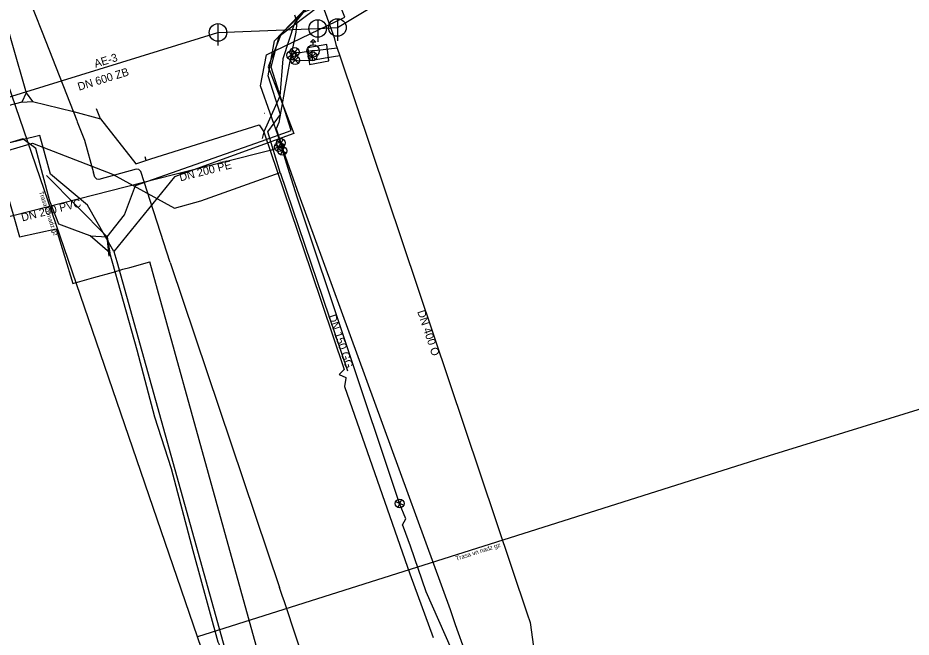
# Model space of a CAD drawing. Extents: x -493753 to -49291, y -1127285 to -112662.
# Drawn here: x -493544.7 to -493443.1, y -1126852.4 to -1126782.1 of the extents above; entities that cross this region are included whole.
import ezdxf

# ---------------------------------------------------------------- set-up
doc = ezdxf.new("R2010")
doc.units = 0
for name, color, linetype in [('Vrstva 1', 7, 'Continuous'), ('Vrstva 11', 7, 'Continuous'), ('Vrstva 12', 7, 'Continuous'), ('Vrstva 15', 7, 'Continuous'), ('Vrstva 17', 7, 'Continuous'), ('Vrstva 19', 7, 'Continuous'), ('Vrstva 20', 7, 'Continuous'), ('Vrstva 22', 7, 'Continuous'), ('Vrstva 24', 7, 'Continuous'), ('Vrstva 25', 7, 'Continuous'), ('Vrstva 26', 7, 'Continuous'), ('Vrstva 35', 7, 'Continuous'), ('Vrstva 39', 7, 'Continuous'), ('Vrstva 6', 7, 'Continuous'), ('Vrstva 9', 7, 'Continuous')]:
    doc.layers.add(name, color=color, linetype=linetype)

# ---------------------------------------------------------------- blocks, each defined once
blk = doc.blocks.new('_UZAVE')
at = {"layer": 'Vrstva 1'}
for p, q in [((-0.035, -0.035), (0.035, 0.035)), ((0.035, -0.035), (-0.035, 0.035))]:
    blk.add_line(p, q, dxfattribs=at)
for radius in [0.05, 0.0025]:
    blk.add_circle((0, 0), radius, dxfattribs=at)
blk = doc.blocks.new('_SACHT')
at = {"layer": 'Vrstva 1'}
blk.add_line((0, 0.035), (0, 0.05), dxfattribs=at)
blk.add_lwpolyline([(-0.015, 0.05), (0, 0.065), (0.015, 0.05), (0.0025, 0.05)], close=True, dxfattribs=at)
blk.add_circle((0, 0), 0.035, dxfattribs=at)
blk = doc.blocks.new('_SACH0')
at = {"layer": 'Vrstva 1'}
blk.add_line((0, 0.05), (0, -0.075), dxfattribs=at)
blk.add_circle((0, 0), 0.05, dxfattribs=at)

msp = doc.modelspace()

# ---------------------------------------------------------------- linework, layer by layer
at = {"layer": 'Vrstva 1'}
for p, q in [((-493527.35, -1126809.84), (-493527.27, -1126810.09)), ((-493527.27, -1126810.09), (-493514.91, -1126846.81))]:
    msp.add_line(p, q, dxfattribs=at)
for points in [[(-493393.38, -1126991.88), (-493403.57, -1126997.06), (-493408.72, -1126999.68), (-493421.9, -1127006.38), (-493451.16, -1126957.48), (-493453.5, -1126951.96), (-493486.26, -1126874.64), (-493487, -1126872.89), (-493487.52, -1126871.61), (-493487.88, -1126870.61), (-493487.89, -1126870.58), (-493488.33, -1126869.34), (-493488.49, -1126868.9), (-493493.92, -1126853.77), (-493494.71, -1126851.57), (-493494.94, -1126850.93), (-493495.49, -1126849.33), (-493512.69, -1126802.2), (-493517.09, -1126789.79), (-493516.41, -1126786.25), (-493507.48, -1126781.99), (-493508.14, -1126780.34), (-493515.01, -1126760.11)], [(-493545.25, -1126775.16), (-493545.2, -1126775.3), (-493544.69, -1126776.61), (-493544.34, -1126777.48), (-493543.65, -1126779.26), (-493541.92, -1126783.67), (-493537.99, -1126793.72), (-493537.93, -1126793.87)], [(-493552.89, -1126777.99), (-493552.72, -1126778.58), (-493545.07, -1126804.92), (-493544.49, -1126806.95), (-493540.33, -1126806.05), (-493538.43, -1126812.26), (-493536.06, -1126811.58), (-493533.82, -1126810.94), (-493532.86, -1126810.67), (-493532.73, -1126810.63), (-493531.96, -1126810.42), (-493529.68, -1126809.77)], [(-493537.93, -1126793.87), (-493537.11, -1126795.97), (-493536.08, -1126799.67)], [(-493527.35, -1126809.84), (-493530.69, -1126799.5), (-493530.94, -1126799.27), (-493531.23, -1126799.24), (-493535.46, -1126800.43), (-493535.71, -1126800.37), (-493535.92, -1126800.15), (-493536.08, -1126799.67)], [(-493321.71, -1127171.3), (-493355.7, -1127126.12), (-493396.16, -1127072.91), (-493440.36, -1127015.46), (-493443.8, -1127011.63), (-493444.46, -1127010.85), (-493446.49, -1127008.27), (-493452.76, -1127000), (-493477.07, -1126967.92), (-493488.61, -1126953.19), (-493508.76, -1126886.04), (-493510.25, -1126878.84), (-493511.22, -1126875.6), (-493511.24, -1126875.56), (-493513.66, -1126867.49), (-493514.58, -1126864.18), (-493529.68, -1126809.77)], [(-493510.11, -1126861.24), (-493510.21, -1126860.93), (-493514.37, -1126848.44), (-493514.62, -1126847.69), (-493514.91, -1126846.81)]]:
    msp.add_lwpolyline(points, dxfattribs=at)
at = {"layer": 'Vrstva 11'}
for points in [[(-493391.29, -1126748.6), (-493406.26, -1126753.68), (-493434.32, -1126750.53), (-493463.4, -1126761.72), (-493469.71, -1126766.76), (-493508.82, -1126780.08), (-493512.23, -1126781.43), (-493514.74, -1126783.85), (-493516.23, -1126787.62), (-493513.31, -1126795.21), (-493526.86, -1126800.13), (-493533.75, -1126808.59)], [(-493533.75, -1126808.59), (-493536.77, -1126803.34), (-493540.96, -1126799.8), (-493542.18, -1126795.43), (-493570.84, -1126802.44), (-493575.99, -1126803.69)], [(-493513.31, -1126795.21), (-493526.86, -1126800.13), (-493533.75, -1126808.59)], [(-493513.31, -1126795.21), (-493526.86, -1126800.13), (-493533.75, -1126808.59)], [(-493533.75, -1126808.59), (-493533.42, -1126809.75)], [(-493533.42, -1126809.75), (-493513.01, -1126882.98), (-493502.23, -1126919.46), (-493495.95, -1126941.27), (-493489.31, -1126964.34), (-493485.28, -1126966.64)]]:
    msp.add_lwpolyline(points, dxfattribs=at)
at = {"layer": 'Vrstva 12'}
for points in [[(-493538.22, -1126806.17), (-493540.02, -1126805.49), (-493541.05, -1126802.89), (-493542.65, -1126796.89), (-493544.12, -1126795.81), (-493550.06, -1126797.58), (-493555.41, -1126799.32), (-493561.25, -1126800.62)], [(-493536.47, -1126806.83), (-493538.22, -1126806.17)], [(-493534.22, -1126808.77), (-493536.47, -1126806.83)], [(-493521.71, -1126853.4), (-493521.89, -1126853.02), (-493524.73, -1126842.64), (-493527.19, -1126833.32), (-493529.1, -1126827.43), (-493531.11, -1126819.83), (-493534.22, -1126808.77)]]:
    msp.add_lwpolyline(points, dxfattribs=at)
at = {"layer": 'Vrstva 15'}
for p, q in [((-493508.34, -1126783.15), (-493499.28, -1126777.71)), ((-493546.35, -1126791.26), (-493521.92, -1126783.71)), ((-493521.92, -1126783.71), (-493510.58, -1126783.26)), ((-493510.58, -1126783.26), (-493508.34, -1126783.15))]:
    msp.add_line(p, q, dxfattribs=at)
at = {"layer": 'Vrstva 20'}
for p, q in [((-493508.37, -1126785.51), (-493509.97, -1126785.67)), ((-493508.37, -1126785.51), (-493508.08, -1126786.38)), ((-493513.6, -1126786.31), (-493513.72, -1126786.74)), ((-493513.72, -1126786.74), (-493513.15, -1126786.87)), ((-493513.53, -1126785.87), (-493513.6, -1126786.31)), ((-493513.53, -1126785.87), (-493513.2, -1126785.93)), ((-493513.2, -1126785.93), (-493512.56, -1126786.01)), ((-493511.25, -1126785.81), (-493512.56, -1126786.01)), ((-493511.17, -1126786.89), (-493511.18, -1126786.42)), ((-493509.75, -1126786.65), (-493511.17, -1126786.89)), ((-493508.08, -1126786.38), (-493509.75, -1126786.65)), ((-493513.15, -1126786.87), (-493512.56, -1126786.93)), ((-493511.17, -1126786.89), (-493512.56, -1126786.93)), ((-493515.01, -1126796.73), (-493515.84, -1126797.08)), ((-493514.74, -1126796.71), (-493515.01, -1126796.73)), ((-493514.77, -1126796.27), (-493514.74, -1126796.71)), ((-493514.74, -1126796.71), (-493514.6, -1126797.17)), ((-493515.84, -1126797.08), (-493526.82, -1126799.86)), ((-493514.6, -1126797.17), (-493513.83, -1126799.61)), ((-493501.26, -1126837.25), (-493501.35, -1126837.02))]:
    msp.add_line(p, q, dxfattribs=at)
for points in [[(-493517.57, -1126763.03), (-493516.2, -1126763.47), (-493508.72, -1126784.27), (-493508.52, -1126785.08), (-493508.37, -1126785.51)], [(-493513.21, -1126781.69), (-493512.97, -1126782.55), (-493513.08, -1126783.68), (-493513.53, -1126785.87)], [(-493509.97, -1126785.67), (-493510.92, -1126785.8), (-493511.1, -1126785.81), (-493511.25, -1126785.81)], [(-493513.72, -1126786.74), (-493513.95, -1126787.97), (-493514.99, -1126793.95), (-493515.32, -1126794.65), (-493514.77, -1126796.27)], [(-493511.18, -1126786.42), (-493511.2, -1126786.15), (-493511.25, -1126785.81)], [(-493508.08, -1126786.38), (-493486.74, -1126849.8), (-493486.41, -1126850.77)], [(-493526.82, -1126799.86), (-493548.86, -1126805.45), (-493554.26, -1126806.96), (-493563.36, -1126808.9), (-493563.61, -1126808.94)], [(-493513.83, -1126799.61), (-493512.93, -1126802.51), (-493501.49, -1126836.64), (-493501.35, -1126837.02)], [(-493481.22, -1126879.4), (-493481.4, -1126879.14), (-493482.12, -1126878.04), (-493488.66, -1126868.52), (-493494.64, -1126855.42), (-493498.24, -1126847.28), (-493500.01, -1126842.1), (-493500.81, -1126839.94), (-493500.94, -1126839.66), (-493500.57, -1126838.98), (-493501.26, -1126837.25)], [(-493486.41, -1126850.77), (-493484.91, -1126861.87), (-493484.36, -1126863.59)]]:
    msp.add_lwpolyline(points, dxfattribs=at)
msp.add_lwpolyline([(-493511.71, -1126785.46), (-493511.51, -1126787.34), (-493509.32, -1126786.92), (-493509.56, -1126785.07)], close=True, dxfattribs=at)
at = {"layer": 'Vrstva 25'}
for p, q in [((-493544.23, -1126791.62), (-493543, -1126791.57)), ((-493535.27, -1126793.54), (-493535.74, -1126792.39)), ((-493516.69, -1126795), (-493516.9, -1126795.77)), ((-493530.08, -1126798.25), (-493530.22, -1126797.85)), ((-493507.56, -1126822.02), (-493508.15, -1126822.58))]:
    msp.add_line(p, q, dxfattribs=at)
for points in [[(-493545.91, -1126734.71), (-493545.66, -1126735.36), (-493539.1, -1126759.13), (-493538.32, -1126763.18), (-493538.36, -1126764.47), (-493540.05, -1126772.25), (-493544.38, -1126776.55), (-493547.5, -1126777.75), (-493547.03, -1126779.18), (-493543.72, -1126790.59), (-493544.23, -1126791.62), (-493555.13, -1126794.46), (-493567.41, -1126798.19)], [(-493511.48, -1126780.5), (-493513.22, -1126782.67), (-493514.53, -1126786.69), (-493514.87, -1126790.94), (-493516.69, -1126795)], [(-493543.72, -1126790.59), (-493543, -1126791.57), (-493538.34, -1126792.7), (-493535.27, -1126793.54), (-493531.25, -1126798.64), (-493529.55, -1126798.07), (-493517.22, -1126794.2), (-493516.69, -1126795)], [(-493516.69, -1126795), (-493511.36, -1126810.77), (-493507.56, -1126822.02)]]:
    msp.add_lwpolyline(points, dxfattribs=at)
at = {"layer": 'Vrstva 26'}
for p, q in [((-493516.62, -1126792.94), (-493516.66, -1126792.93)), ((-493508.15, -1126822.58), (-493507.39, -1126822.92)), ((-493507.37, -1126822.99), (-493507.55, -1126823.96)), ((-493507.39, -1126822.92), (-493507.37, -1126822.99)), ((-493507.55, -1126823.96), (-493500.1, -1126845.26)), ((-493500.1, -1126845.26), (-493497.43, -1126852.5))]:
    msp.add_line(p, q, dxfattribs=at)
at = {"layer": 'Vrstva 35'}
for points in [[(-493514.84, -1126799.64), (-493516.25, -1126795), (-493514.82, -1126793.03), (-493516.22, -1126788.64), (-493515.51, -1126784.66), (-493511.76, -1126780.79), (-493506.84, -1126778.85), (-493510.73, -1126766.78), (-493511.57, -1126763.73), (-493507.29, -1126761.97), (-493506.33, -1126760.82), (-493503.65, -1126739.51), (-493502.66, -1126732.73)], [(-493564.4, -1126802.63), (-493559.61, -1126801.23), (-493543.03, -1126796.31), (-493533.91, -1126799.81), (-493526.85, -1126803.67), (-493523.88, -1126802.84), (-493514.84, -1126799.64), (-493507.2, -1126822.18)]]:
    msp.add_lwpolyline(points, dxfattribs=at)
at = {"layer": 'Vrstva 39'}
for points in [[(-493534.53, -1126806.94), (-493532.56, -1126804.44), (-493531.29, -1126801.12), (-493516.96, -1126796.08), (-493513.58, -1126794.87), (-493515.88, -1126787.64), (-493514.95, -1126784.12), (-493510.44, -1126780.73), (-493472.56, -1126767.69), (-493465.56, -1126763.09), (-493458.46, -1126760.65), (-493452.37, -1126758.7), (-493435.03, -1126752.8), (-493415.49, -1126755.56), (-493405.37, -1126755.91)], [(-493534.53, -1126806.94), (-493532.56, -1126804.44), (-493531.29, -1126801.12), (-493516.96, -1126796.08), (-493513.58, -1126794.87)], [(-493534.53, -1126806.94), (-493541.43, -1126799.96)], [(-493536.47, -1126806.83), (-493534.53, -1126806.94)], [(-493534.28, -1126809.15), (-493534.53, -1126806.94)], [(-493534.53, -1126806.94), (-493534.22, -1126808.77)]]:
    msp.add_lwpolyline(points, dxfattribs=at)
at = {"layer": 'Vrstva 6'}
for points in [[(-493524.27, -1126852.41), (-493556.88, -1126757.31)], [(-493388.54, -1126809.96), (-493459.25, -1126831.84)], [(-493459.25, -1126831.84), (-493524.27, -1126852.41)], [(-493519.48, -1126866.31), (-493524.27, -1126852.41)]]:
    msp.add_lwpolyline(points, dxfattribs=at)

# ---------------------------------------------------------------- block references
at = {"layer": 'Vrstva 17', "xscale": 19.997500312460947, "yscale": 19.997500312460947}
for p in [(-493521.92, -1126783.71), (-493510.58, -1126783.26), (-493508.34, -1126783.15)]:
    msp.add_blockref('_SACH0', p, dxfattribs=at)
at = {"layer": 'Vrstva 22'}
for name, p, xscale, yscale in [('_SACHT', (-493511.1, -1126785.81), 19.997500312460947, 19.997500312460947), ('_UZAVE', (-493513.2, -1126785.93), 9.998750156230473, 9.998750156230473), ('_UZAVE', (-493513.15, -1126786.87), 9.998750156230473, 9.998750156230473)]:
    msp.add_blockref(name, p, dxfattribs=dict(at, xscale=xscale, yscale=yscale))
for p, xscale, yscale, rotation in [((-493513.6, -1126786.31), 9.998750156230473, 9.998750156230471, -102.47813688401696), ((-493511.18, -1126786.42), 9.998750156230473, 9.998750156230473, 87.3096027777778), ((-493514.77, -1126796.27), 9.998750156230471, 9.99875015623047, 105.559497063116), ((-493515.01, -1126796.73), 9.998750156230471, 9.998750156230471, -160.911647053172), ((-493514.6, -1126797.17), 9.998750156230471, 9.998750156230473, -72.38129362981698), ((-493501.26, -1126837.25), 9.998750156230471, 9.998750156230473, 111.37062207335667)]:
    msp.add_blockref('_UZAVE', p, dxfattribs=dict(at, xscale=xscale, yscale=yscale, rotation=rotation))

# ---------------------------------------------------------------- texts
at = {"layer": 'Vrstva 19'}
for s, p in [('AE-3', (-493535.85, -1126787.73)), ('DN 600 ZB', (-493537.72, -1126790.34))]:
    msp.add_text(s, height=0.91, rotation=17.1736, dxfattribs=at).set_placement(p)
at = {"layer": 'Vrstva 24'}
for s, height, rotation, p in [('DN 200 PE', 0.91, 14.2235, (-493526.19, -1126800.64)), ('DN 500 O', 0.16, 14.1652, (-493521.85, -1126798.6)), ('DN 200 PVC', 0.91, 14.2235, (-493544.17, -1126805.2)), ('DN 150 GG', 0.91, 288.5311, (-493509.39, -1126815.94)), ('DN 400 O', 0.91, 288.5923, (-493499.27, -1126815.44))]:
    msp.add_text(s, height=height, rotation=rotation, dxfattribs=at).set_placement(p)
at = {"layer": 'Vrstva 9'}
for rotation, p in [(288.927, (-493542.29, -1126801.86)), (17.5553, (-493494.8, -1126843.76))]:
    msp.add_text('Trasa vn nadz gz', height=0.5, rotation=rotation, dxfattribs=at).set_placement(p)

doc.saveas('drawing.dxf')
